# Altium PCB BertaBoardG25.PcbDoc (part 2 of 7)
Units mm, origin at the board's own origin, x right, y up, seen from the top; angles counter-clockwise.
Board outline 160 x 160 mm, 4 copper layers (Top, GND Plane, Power Plane, Bottom), stack 1.344 mm thick; 17 components, 112 nets, 2311 pads, 138 vias.
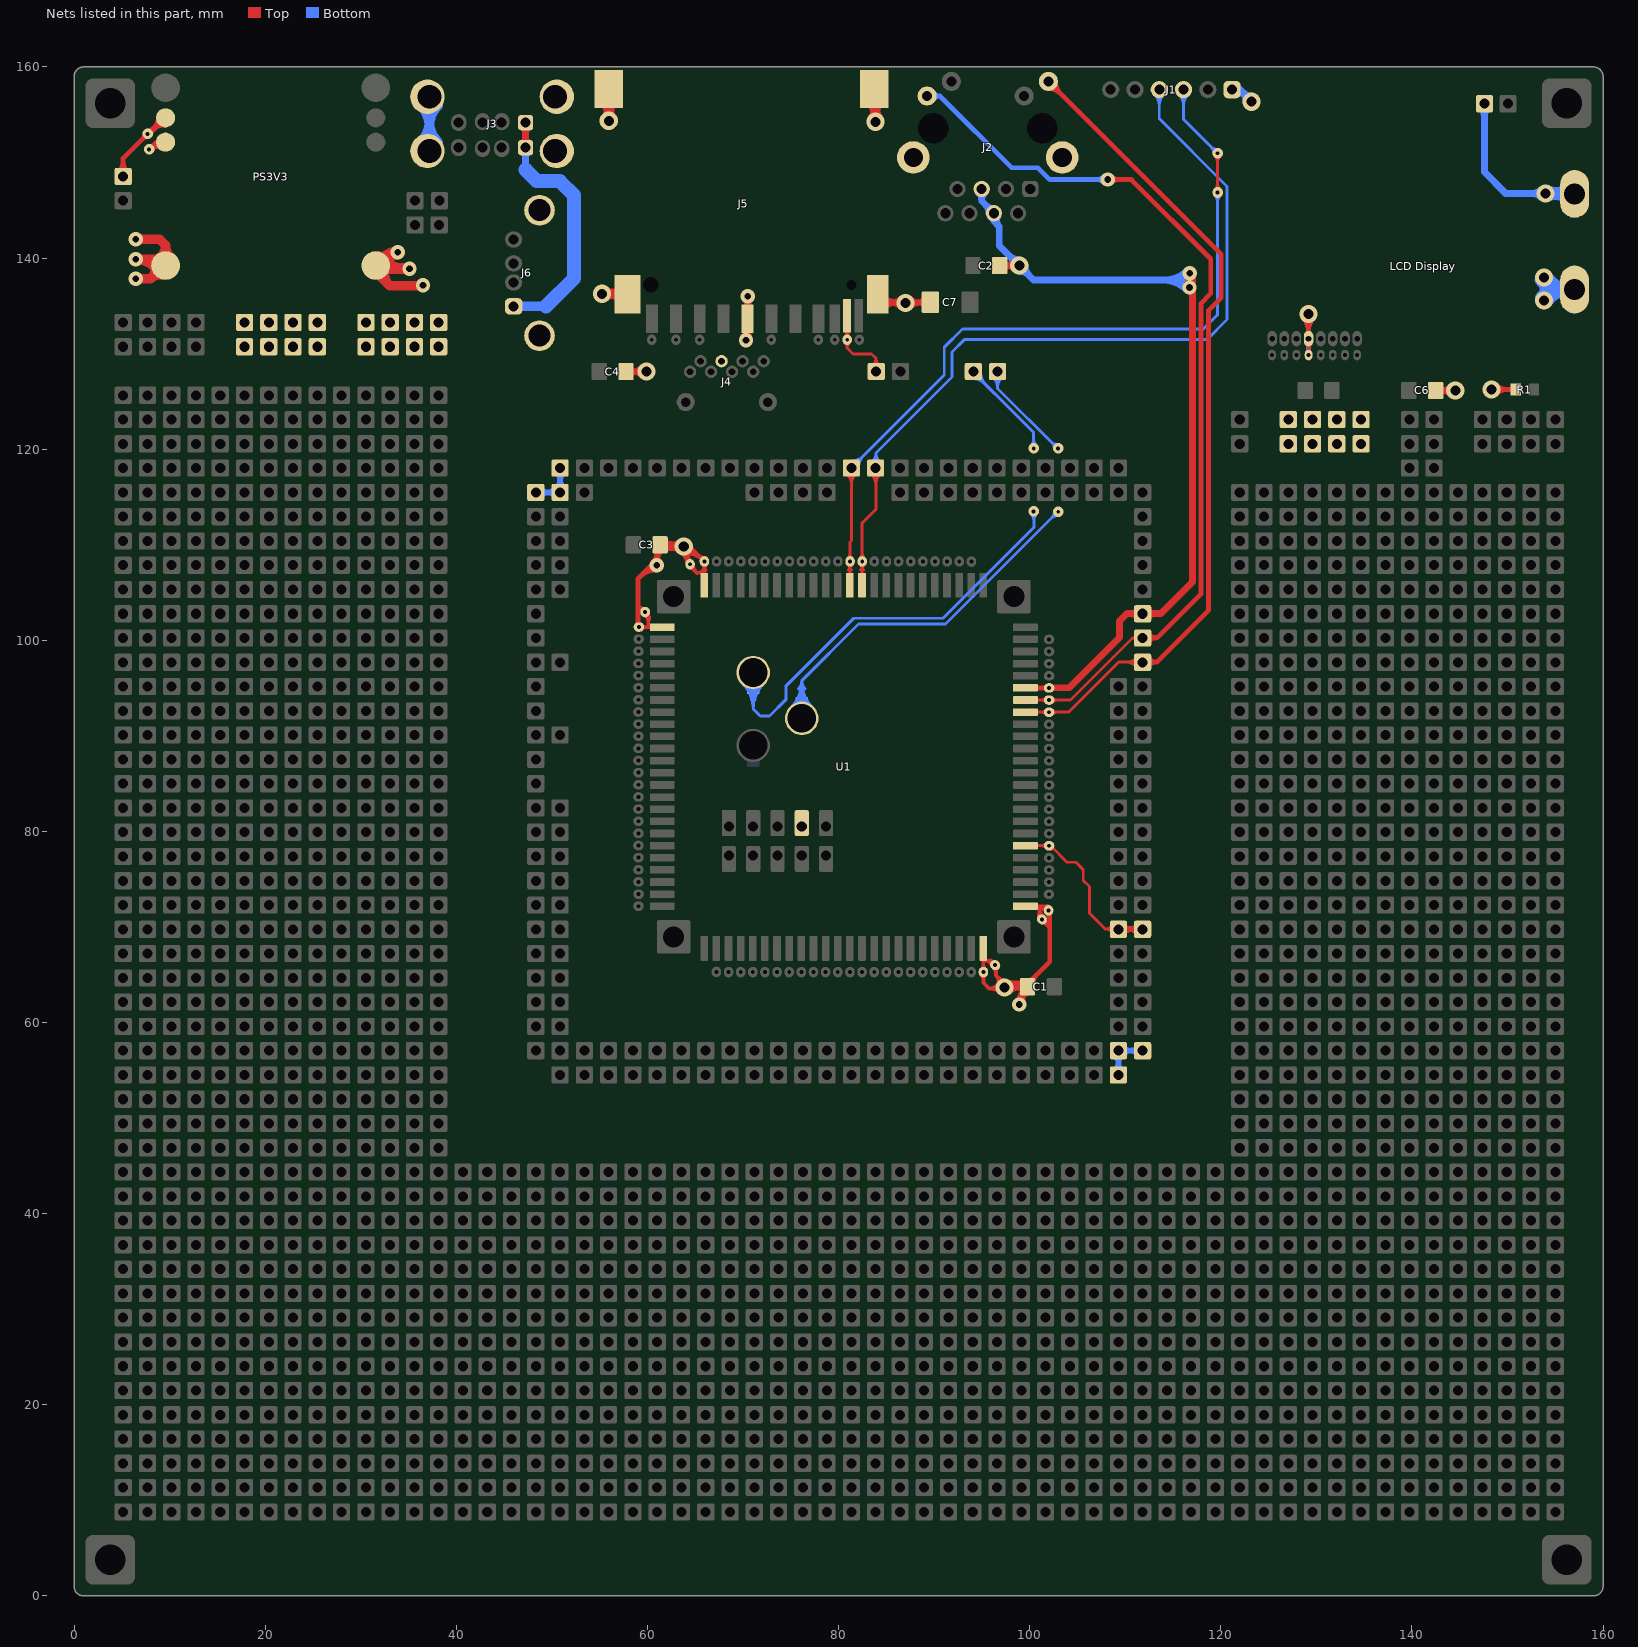
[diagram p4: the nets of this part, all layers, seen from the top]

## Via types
v1: diameter 1.5, hole 0.7, Top to Bottom, tented both sides, 54 vias
v2: diameter 1.1, hole 0.4, Top to Bottom, tented both sides, 49 vias
v3: diameter 1.9, hole 1.05, Top to Bottom, tented both sides, 17 vias
v4: diameter 1.9, hole 1.05, Top to Bottom, 16 vias
v5: diameter 0.9, hole 0.4, Top to Bottom, tented both sides, 2 vias

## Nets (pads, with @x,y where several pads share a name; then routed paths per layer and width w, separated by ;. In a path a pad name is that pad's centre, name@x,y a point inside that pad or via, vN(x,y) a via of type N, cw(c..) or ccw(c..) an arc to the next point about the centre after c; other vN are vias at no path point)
3V3: "LCD Display.4" "LCD Display.9" C1.1 C3.1 C4.1 C6.2 J1.1 J4.4 J5.4 pad.0@17.842,130.72 pad.0@17.842,133.26 pad.0@20.382,130.72 pad.0@20.382,133.26 pad.0@22.922,130.72 pad.0@22.922,133.26 pad.0@25.462,130.72 pad.0@25.462,133.26 pad.0@48.322,115.48 pad.0@50.862,115.48 pad.0@50.862,118.02 pad.0@59.11,101.385 pad.0@59.761,102.96 pad.0@64.464,107.961 pad.0@65.964,108.261 pad.0@95.159,65.279 pad.0@96.387,66.017 pad.0@101.287,70.796 pad.0@101.977,71.74 pad.0@109.282,54.52 pad.0@109.282,57.06 pad.0@111.822,57.06 pad.0@127.062,120.56 pad.0@127.062,123.1 pad.0@129.183,129.853 pad.0@129.602,120.56 pad.0@129.602,123.1 pad.0@132.142,120.56 pad.0@132.142,123.1 pad.0@134.682,120.56 pad.0@134.682,123.1 PS3V3.4 R1.2 U1.7 U1.E24 U1.N1 U1.S1 U1.W24 | length 300.1
  Top w0.3: 128.935,131.014 cw(c128.338,130.416) 129.183,130.416 cw(c130.028,130.416) 129.43,131.014 ; pad.0@129.006,130.179 ccw(c128.579,130.606) 129.183,130.606 ccw(c129.786,130.606) pad.0@129.36,130.179 ; pad.0@129.183,130.168 129.183,131.561 129.183,131.57
  Top w0.35: pad.0@59.267,101.375 U1.E24@61.551,101.375 ; pad.0@59.389,101.155 cw(c59.92,100.624) 59.92,101.375 ; pad.0@59.389,101.614 ccw(c59.968,102.193) 59.968,101.375 ; 60.102,101.375 60.102,102.24 ; U1.E24@60.603,101.375 ccw(c60.603,101.908) U1.E24@61.042,101.604 ; U1.E24@61.272,101.375 ccw(c61.272,101.445) U1.E24@61.329,101.405 ; pad.0@65.734,107.981 cw(c65.221,107.468) 65.946,107.468 ; 65.771,107.311 cw(c65.202,107.772) 65.202,107.04 U1.S1@65.889,107.04 ; 65.787,107.329 ccw(c65.403,107.713) 65.946,107.713 ccw(c66.489,107.713) 66.105,107.329 ; U1.S1@65.946,105.77 pad.0@65.946,108.295 ; 65.946,107.384 cw(c66.79,107.384) pad.0@66.193,107.981 ; pad.0@94.929,65.558 ccw(c94.374,66.113) 95.159,66.113 ccw(c95.943,66.113) pad.0@95.389,65.558 ; U1.N1@94.997,67.211 cw(c94.607,66.82) U1.N1@95.159,66.82 ; U1.N1@95.156,67.77 95.159,67.767 pad.0@95.159,65.279 ; U1.N1@95.159,66.833 cw(c95.693,66.833) U1.N1@95.315,67.211 ; 95.729,66.5 cw(c95.729,65.805) pad.0@96.375,66.061 ; 95.901,66.5 95.213,66.5 cw(c95.213,65.6) pad.0@96.05,65.932 ; U1.W24@99.551,72.165 pad.0@101.836,72.165 ; U1.W24@99.773,72.195 ccw(c99.831,72.235) U1.W24@99.831,72.165 ; U1.W24@100.064,72.348 ccw(c100.502,72.652) U1.W24@100.502,72.118 ; U1.W24@100.289,72.165 cw(c100.289,70.102) pad.0@101.747,71.561 ; U1.W24@100.496,72.348 cw(c99.613,71.062) pad.0@101.172,71.062 ; 101.001,71.3 101.001,72.165 ccw(c102.505,72.165) pad.0@101.475,71.069 ; 101.001,71.355 ccw(c101.744,71.355) pad.0@101.235,70.813 ; 101.134,72.165 cw(c101.134,70.947) pad.0@101.995,71.808
  Top w0.4: C3.1@61.49,110.008 ccw(c62.373,110.654) 62.373,109.56 ; C3.1@61.753,109.666 cw(c62.945,108.474) v4@62.945,110.16 ; C3.1@61.753,110.514 ccw(c62.609,111.371) 62.609,110.16 ; C3.1@61.813,110.244 ccw(c63.161,111.23) v4@63.161,109.56 ; C3.1@61.902,109.34 C3.1@62.122,109.56 ; 62.447,110.16 cw(c62.447,108.834) v4@63.519,109.614 ; 62.618,109.56 cw(c62.618,108.636) v4@63.271,109.289 ; 62.787,109.56 ccw(c62.787,110.358) v4@63.493,109.984 ; 62.812,110.16 ccw(c62.812,110.809) v4@63.271,110.35 ; v4@63.139,110.171 cw(c62.122,110.712) C3.1@62.122,109.56 ; v4@63.195,109.378 ccw(c61.661,108.263) 61.661,110.16 64.082,110.16 65.946,108.295 ccw(c64.054,106.404) v4@63.857,109.072 ; v4@63.76,109.846 ccw(c64.432,109.417) 63.868,108.853 ; v4@63.798,109.869 cw(c63.884,108.703) 64.711,109.53 ; v4@63.828,109.47 cw(c63.969,107.553) 65.329,108.913 ; v4@64.097,109.631 ccw(c64.861,109.143) 64.22,108.501 ; pad.0@64.164,108.015 ccw(c62.892,108.03) v4@63.791,108.93 ; v4@64.434,109.416 ccw(c65.291,108.868) pad.0@64.572,108.149 ; pad.0@64.464,107.611 cw(c64.464,107.208) 64.748,107.493 ; pad.0@64.764,107.911 ccw(c65.809,107.911) 65.07,107.171 ; 65.202,107.04 64.572,107.67 pad.0@64.572,108.149 ; 65.395,108.847 ccw(c65.964,109.415) pad.0@65.964,108.611 ; 65.475,108.766 cw(c65.019,108.311) pad.0@65.664,108.311 ; pad.0@94.947,65.016 cw(c94.441,64.51) 95.156,64.51 ; 95.156,64.498 cw(c95.889,64.498) pad.0@95.371,65.016 ; pad.0@95.156,65.279 95.156,64.165 95.761,63.56 ; 95.86,63.56 cw(c95.86,62.159) v4@96.851,63.149 ; pad.0@96.053,66.079 ccw(c95.527,66.126) 95.901,66.5 ; pad.0@96.211,65.769 cw(c95.571,65.129) 96.476,65.129 ; pad.0@96.321,66.351 cw(c96.268,66.867) 95.901,66.5 ; 96.476,65.385 cw(c97.019,65.385) pad.0@96.635,65.769 ; v4@96.683,63.953 ccw(c95.821,64.291) 96.476,64.945 ; 96.715,64.705 ccw(c97.381,65.371) v4@97.381,64.43 ; v4@96.756,64.094 cw(c95.761,64.753) 95.761,63.56 ; 96.908,64.513 cw(c96.442,64.048) v4@97.055,63.807 ; v4@97.479,64.2 cw(c97.479,61.555) C1.1@99.35,63.425 ; v4@97.71,63.559 cw(c98.628,63.222) 98.628,64.2 ; v4@97.911,63.149 cw(c98.902,62.159) 98.902,63.56 ; v4@98.015,64.08 ccw(c98.96,64.678) 98.96,63.56 ; v4@98.036,63.315 cw(c98.663,62.966) 98.477,63.658 ; v4@98.085,63.421 cw(c99.201,63.012) 99.201,64.2 97.221,64.2 96.476,64.945 ; v4@98.109,63.56 ccw(c98.109,65.314) C1.1@99.349,64.074 ; 98.445,64.2 cw(c98.445,62.52) C1.1@99.632,63.708 ; 98.542,63.56 cw(c98.542,62.417) C1.1@99.349,63.225 ; C1.1@99.182,63.747 cw(c98.96,63.784) 98.96,63.56 ; C1.1@99.233,63.388 ccw(c98.96,63.256) 98.96,63.56 ; C3.1@62.122,109.56 v4@63.161,109.56 ; v4@63.161,109.56 v4@63.791,108.93 ; v4@63.791,108.93 pad.0@64.572,108.149 ; 95.761,63.56 98.96,63.56 ; 95.901,66.5 96.476,65.925 96.476,64.945
  Top w0.5: C4.1@57.759,128.122 v4@59.9,128.122 ; C4.1@58.148,127.733 cw(c59.087,126.794) 59.087,128.122 cw(c59.087,129.45) C4.1@58.148,128.511 ; C4.1@58.208,128.122 cw(c58.208,126.427) v4@59.406,127.625 ; C4.1@58.215,128.122 ccw(c58.215,129.807) v4@59.406,128.615 ; 59.002,102.128 ccw(c59.803,102.128) pad.0@59.236,101.561 ; 59.187,106.625 cw(c60.961,104.851) v1@60.961,107.36 ; pad.0@59.267,101.375 59.002,101.64 59.002,106.44 61.002,108.44 C3.1@61.002,109.44 ; v4@59.272,127.814 ccw(c58.888,127.627) 58.778,128.039 ccw(c58.572,128.809) v4@59.28,128.442 ; v4@59.274,128.432 cw(c58.886,128.625) 58.773,128.206 cw(c58.565,127.429) v4@59.28,127.798 ; pad.0@59.702,102.667 cw(c59.578,102.158) 60.102,102.158 ; pad.0@59.745,103.259 cw(c59.683,104.221) 59.002,103.54 60.102,102.44 ; pad.0@60.001,102.838 ccw(c60.386,102.724) 60.102,102.44 ; 60.04,107.478 cw(c60.961,106.558) v1(60.961,107.86) ; 60.102,102.24 60.102,102.44 ; v1@60.608,108.213 ccw(c59.656,109.165) C3.1@61.002,109.165 ; v1@60.714,108.294 ccw(c60.296,109.026) 61.11,108.808 ccw(c61.649,108.664) v1@61.286,108.24 ; v1@61.002,108.403 cw(c62.151,108.403) C3.1@61.595,109.409 ; 61.002,108.969 ccw(c62.07,108.969) v1@61.315,108.213 ; v1@98.651,62.333 ccw(c98.26,63.01) 99.015,62.808 ; v1@98.694,62.355 ccw(c98.548,62.676) 98.901,62.676 ; v1@98.901,61.694 cw(c100.405,61.694) C1.1@99.943,63.126 ; v1@98.901,62.381 cw(c100.183,62.381) C1.1@99.789,63.602 ; 99.006,62.781 cw(c99.774,62.013) C1.1@99.774,63.099 ; 99.017,62.814 ccw(c99.48,62.69) v1@99.196,62.303 ; v1@99.107,62.355 cw(c99.253,62.676) 98.901,62.676 ; C1.1@99.172,62.948 ccw(c99.928,62.193) v1(98.901,61.9) 98.901,62.676 ; C1.1@99.227,63.593 cw(c98.099,63.478) 98.901,62.676 ; v1@99.381,62.037 cw(c100.863,62.46) 99.774,63.549 98.901,62.676 ; C1.1@99.774,64.399 ccw(c99.774,65.226) C1.1@100.358,64.641 ; C1.1@100.101,64.1 100.101,64.384 102.101,66.384 102.101,71.9 pad.0@101.836,72.165 ; C1.1@100.324,63.849 cw(c102.153,63.849) 100.859,65.143 ; 101.001,71.3 101.001,71.1 102.101,70 ; pad.0@101.323,70.511 cw(c101.323,69.867) 101.778,70.322 ; pad.0@101.573,70.761 ccw(c102.136,70.761) 101.738,70.363 ; pad.0@101.8,71.514 cw(c101.076,70.789) 102.101,70.789 ; v3@128.666,133.665 cw(c127.419,132.418) 129.183,132.418 ; 129.006,132.038 ccw(c128.579,132.465) 129.183,132.465 ccw(c129.786,132.465) 129.36,132.038 ; v3(129.161,134.16) 129.183,134.138 129.183,131.561 ; 129.183,132.522 cw(c130.799,132.522) v3@129.656,133.665 ; C6.2@142.479,126.143 v4(144.537,126.144) ; C6.2@142.844,126.143 ccw(c142.844,127.838) v4@144.042,126.639 ; C6.2@142.851,126.143 cw(c142.851,124.458) v4@144.042,125.649 ; C6.2@142.868,125.754 cw(c143.807,124.815) 143.807,126.143 cw(c143.807,127.471) C6.2@142.868,126.532 ; v4@143.897,125.863 ccw(c143.29,125.596) 143.462,126.236 ccw(c143.56,126.602) v4@143.903,126.441 ; v4@143.896,126.426 cw(c143.284,126.695) 143.457,126.049 cw(c143.557,125.676) v4@143.906,125.843 ; v4@148.31,126.24 R1.2@150.451,126.24 ; v4@148.804,125.749 cw(c149.988,124.566) 149.988,126.24 ; v4@148.804,126.739 ccw(c150.01,127.946) 150.01,126.24 ; 150.137,126.24 ccw(c150.137,126.975) R1.2@150.657,126.455 ; 150.153,126.24 cw(c150.153,125.527) R1.2@150.657,126.031
  Top w0.7: v1@70.028,131.693 ccw(c68.943,132.778) J5.4@70.477,132.778 ; v1@70.111,131.756 ccw(c69.664,132.53) J5.4@70.527,132.298 ; v1@70.218,135.717 cw(c69.591,135.091) J5.4@70.477,135.091 ; J5.4@70.283,132.583 cw(c69.813,132.114) 70.477,132.114 cw(c71.141,132.114) J5.4@70.672,132.583 ; J5.4@70.283,134.722 ccw(c69.813,135.192) 70.477,135.192 ccw(c71.141,135.192) J5.4@70.672,134.722 ; v1@70.477,131.5 J5.4@70.477,133.653 v1@70.477,136 ; J5.4@70.477,134.978 cw(c71.523,134.978) v1@70.783,135.717 ; J5.4@70.553,132.398 ccw(c71.556,132.129) v1@70.657,131.61
  Top w1: v1(6.447,141.967) 8.947,141.967 9.579,141.335 ; v1(6.457,137.837) 8.017,137.837 9.398,139.219 PS3V3.4@9.579,139.219 ; PS3V3.4@8.579,139.21 cw(c6.659,139.195) 8.017,137.837 cw(c9.066,136.788) PS3V3.4@9.373,138.24 ; PS3V3.4@8.755,138.653 ccw(c6.447,137.068) v1(6.447,139.867) 8.93,139.867 PS3V3.4@9.579,139.219 ; PS3V3.4@8.944,139.991 ccw(c7.839,141.335) 9.579,141.335 ; PS3V3.4@10.214,139.991 cw(c11.319,141.335) 9.579,141.335 ; PS3V3.4@9.579,139.219 9.579,141.335
  Bottom w0.35: pad.0@48.322,115.48 pad.0@50.862,115.48 pad.0@50.862,118.02 ; pad.0@48.587,115.214 cw(c49.227,114.574) 49.227,115.48 cw(c49.227,116.385) pad.0@48.587,115.745 ; pad.0@48.834,114.967 cw(c50.072,113.729) 50.072,115.48 cw(c50.072,117.23) pad.0@48.834,115.992 ; pad.0@48.919,115.069 cw(c49.471,114.69) 49.645,115.337 ; pad.0@48.919,115.89 ccw(c49.471,116.269) 49.645,115.622 ; pad.0@48.95,115.117 cw(c49.861,114.591) 49.589,115.607 ; pad.0@48.95,115.842 ccw(c49.861,116.368) 49.589,115.352 ; pad.0@50.349,114.967 ccw(c49.111,113.729) 49.111,115.48 ccw(c49.111,117.23) 50.349,115.992 ccw(c49.111,117.23) 50.862,117.23 ccw(c52.612,117.23) pad.0@51.374,115.992 ; pad.0@50.349,117.507 cw(c49.111,116.269) 50.862,116.269 cw(c52.612,116.269) pad.0@51.374,117.507 ; pad.0@50.451,117.422 cw(c50.072,116.87) 50.719,116.697 ; pad.0@50.499,117.392 cw(c49.973,116.48) 50.99,116.753 ; pad.0@50.597,115.214 ccw(c49.956,114.574) 49.956,115.48 ccw(c49.956,116.385) 50.597,115.745 ccw(c49.956,116.385) 50.862,116.385 ccw(c51.767,116.385) pad.0@51.127,115.745 ; pad.0@50.597,117.754 cw(c49.956,117.114) 50.862,117.114 cw(c51.767,117.114) pad.0@51.127,117.754 ; 50.734,116.753 cw(c51.75,116.48) pad.0@51.224,117.392 ; 51.005,116.697 cw(c51.651,116.87) pad.0@51.272,117.422 ; pad.0@108.769,55.032 ccw(c107.531,56.27) 109.282,56.27 ccw(c111.032,56.27) pad.0@109.794,55.032 ; pad.0@108.769,56.547 cw(c107.531,55.309) 109.282,55.309 cw(c111.032,55.309) 109.794,56.547 cw(c111.032,55.309) 111.032,57.06 cw(c111.032,58.81) pad.0@109.794,57.572 ; pad.0@108.871,56.462 cw(c108.492,55.91) 109.139,55.737 ; pad.0@108.919,56.432 cw(c108.393,55.52) 109.41,55.793 ; pad.0@109.017,54.785 ccw(c108.376,55.425) 109.282,55.425 ccw(c110.187,55.425) pad.0@109.547,54.785 ; pad.0@109.017,56.794 cw(c108.376,56.154) 109.282,56.154 cw(c110.187,56.154) 109.547,56.794 cw(c110.187,56.154) 110.187,57.06 cw(c110.187,57.965) pad.0@109.547,57.325 ; 109.154,55.793 cw(c110.17,55.52) pad.0@109.644,56.432 ; pad.0@109.282,54.52 pad.0@109.282,57.06 pad.0@111.822,57.06 ; 109.425,55.737 cw(c110.071,55.91) pad.0@109.692,56.462 ; pad.0@109.879,56.649 cw(c110.431,56.27) 110.605,56.917 ; pad.0@109.879,57.47 ccw(c110.431,57.849) 110.605,57.202 ; pad.0@109.91,56.697 cw(c110.821,56.171) 110.549,57.187 ; pad.0@109.91,57.422 ccw(c110.821,57.948) 110.549,56.932 ; pad.0@111.309,56.547 ccw(c110.071,55.309) 110.071,57.06 ccw(c110.071,58.81) pad.0@111.309,57.572 ; pad.0@111.557,56.794 ccw(c110.916,56.154) 110.916,57.06 ccw(c110.916,57.965) pad.0@111.557,57.325
  Bottom w0.5: J1.1@121.055,158 cw(c121.363,157.062) J1.1@122.061,157.76 ; J1.1@121.18,157.62 122.201,157.62 ; J1.1@121.211,157.525 cw(c121.647,156.196) 122.636,157.185 ; J1.1@121.367,157.05 cw(c121.931,155.33) v3@123.211,156.61 ; J1.1@121.704,157.328 cw(c122.201,157.052) 122.201,157.62 ; J1.1@121.704,157.912 ccw(c122.201,158.188) 122.201,157.62 ; J1.1@121.795,157.67 cw(c121.079,156.429) v3@122.511,156.382 ; 122.443,157.378 ccw(c123.211,158.146) v3@123.211,157.06 ; 122.518,157.253 cw(c122.025,156.398) v3@123.011,156.366 ; v3@122.527,156.509 ccw(c121.346,156.766) 122.201,157.62 ; v3(123.211,156.36) v3@123.211,156.61 ; v3@128.666,133.665 cw(c127.419,132.418) 129.183,132.418 ; 129.006,131.085 cw(c128.579,130.658) 129.183,130.658 cw(c129.786,130.658) 129.36,131.085 ; 129.006,132.038 ccw(c128.579,132.465) 129.183,132.465 ccw(c129.786,132.465) 129.36,132.038 ; pad.0@129.161,130.16 129.183,130.181 129.183,131.561 129.183,134.138 v3(129.161,134.16) ; 129.183,132.522 cw(c130.799,132.522) v3@129.656,133.665 ; 122.201,157.62 v3@123.211,156.61
  Bottom w1: v3@153.345,137.668 ccw(c155.071,138.747) 155.071,136.711 ; v3@153.36,135.874 cw(c154.962,134.759) 154.962,136.711 ; 153.868,136.711 156.876,136.711 ; v3@154.181,135.303 cw(c156.876,133.429) 156.876,136.711 ; v3@154.193,138.198 ccw(c156.876,139.876) 156.876,136.711 ; 156.311,136.004 ccw(c154.604,134.297) 154.604,136.711 ccw(c154.603,139.126) 156.311,137.418
  other v1: 70.311,131.41 70.501,136
  other v3: 153.811,135.56 153.811,137.96
  other v4: 97.381,63.68 63.802,109.819 148.309,126.244 59.901,128.12
"3V3 ETH": C2.1 J2.4 J2.5 pad.0@102.032,95.017 pad.0@111.822,102.78 U1.W6 | length 117.5
  Top w0.5: C2.1@96.858,139.211 v4(98.916,139.213) ; C2.1@97.223,139.211 ccw(c97.223,140.906) v4@98.421,139.708 ; C2.1@97.23,139.211 cw(c97.23,137.526) v4@98.421,138.718 ; C2.1@97.247,138.822 cw(c98.186,137.883) 98.186,139.211 cw(c98.186,140.539) C2.1@97.247,139.6 ; v4@98.276,138.931 ccw(c97.669,138.664) 97.841,139.304 ccw(c97.939,139.67) v4@98.282,139.509 ; v4@98.276,139.494 cw(c97.663,139.764) 97.836,139.117 cw(c97.936,138.744) v4@98.285,138.911 ; 100.891,95.02 100.894,95.017 pad.0@102.032,95.017 ; pad.0@101.806,94.841 ccw(c101.379,94.414) 101.379,95.017 ccw(c101.379,95.621) pad.0@101.806,95.194
  Top w0.7: pad.0@102.032,95.025 104.126,95.025 109.401,100.299 109.401,102.02 110.19,102.81 pad.0@111.741,102.81 ; 110.421,102.81 cw(c110.421,101.379) pad.0@111.433,102.391 ; 110.567,102.81 ccw(c110.567,104.035) pad.0@111.433,103.168 ; pad.0@111.691,102.76 pad.0@111.741,102.81 ; pad.0@111.831,102.9 pad.0@111.741,102.81 ; pad.0@112.211,102.391 cw(c113.222,101.379) 113.222,102.81 ; pad.0@112.211,103.168 ccw(c113.077,104.035) 113.077,102.81 ; v1@116.469,137.231 ccw(c115.514,138.41) 117.031,138.41 117.031,106.1 113.741,102.81 pad.0@111.741,102.81 ; v1@116.478,138.127 cw(c115.142,136.791) v1@117.031,136.791
  Bottom w0.7: J2.5@94.626,146.874 cw(c93.772,146.021) 94.979,146.021 cw(c96.186,146.021) J2.5@95.333,146.874 ; J2.5@94.979,147.228 94.979,145.958 J2.4@96.249,144.688 96.249,143.851 96.801,143.3 ; J2.4@95.749,144.688 ccw(c94.542,144.688) 95.396,145.541 ccw(c96.249,146.395) J2.4@96.249,145.188 ; J2.4@96.673,144.422 ccw(c97.442,143.941) 96.801,143.3 ; 97.878,140.243 ccw(c98.916,141.281) v4@98.916,139.813 ; 97.898,140.223 cw(c96.888,139.213) v4@98.316,139.213 ; v4@98.916,138.613 cw(c98.916,137.184) 99.927,138.194 ; v4@99.516,139.213 ccw(c100.985,139.213) 99.946,138.174 ; 113.848,137.71 cw(c113.848,134.047) v1@116.438,136.637 ; 114.105,137.71 ccw(c114.105,141.066) v1@116.478,138.693 ; 115.538,137.71 cw(c115.538,135.737) v1@116.933,137.132 ; 115.795,137.71 ccw(c115.795,139.376) v1@116.973,138.198 ; v1@116.941,137.71 100.411,137.71 96.801,141.32 96.801,143.3
  other v1: 116.721,136.92 116.761,138.41
3V3AUX: PS3V3.3 | length 7.4
  Top w0.5: v2@7.861,151.66 ccw(c7.861,152.384) 8.373,151.872 ccw(c8.885,151.36) v2@8.161,151.36 ; v2@8.151,151.282 cw(c9.379,150.953) PS3V3.3@8.743,152.054 ; v2@8.159,151.398 cw(c8.602,151.456) 8.379,151.843 ; 8.299,151.797 cw(c8.946,151.15) PS3V3.3@9.443,151.919 ; PS3V3.3@9.172,151.499 ccw(c8.602,150.618) v2(7.861,151.36) 8.63,152.129 PS3V3.3@9.579,152.129
5V0: J3.1 J3.5 J6.1 pad.0@30.542,130.72 pad.0@30.542,133.26 pad.0@33.082,130.72 pad.0@33.082,133.26 pad.0@35.622,130.72 pad.0@35.622,133.26 pad.0@38.162,130.72 pad.0@38.162,133.26 PS3V3.5 | length 65.8
  Top w0.7: J3.1@46.934,151.871 ccw(c46.166,152.639) 47.252,152.639 ccw(c48.339,152.639) J3.1@47.57,151.871 ; J3.5@46.934,153.855 cw(c46.166,153.086) 47.252,153.086 cw(c48.339,153.086) J3.5@47.57,153.855 ; J3.1@47.252,151.553 J3.5@47.252,154.173
  Top w1: PS3V3.5@31.785,140.197 ccw(c32.092,141.649) v1@33.141,140.6 ; PS3V3.5@32.205,139.664 cw(c33.861,138.008) v1@33.861,140.35 ; PS3V3.5@32.228,138.57 PS3V3.5@31.579,139.219 ; PS3V3.5@32.286,138.511 cw(c33.072,137.725) 33.072,138.837 ; PS3V3.5@32.286,139.926 ccw(c34.914,142.554) v1@34.914,138.837 ; PS3V3.5@32.464,139.428 cw(c34.082,138.494) v1@33.887,140.351 ; PS3V3.5@32.541,138.945 ccw(c34.347,138.43) 33.019,137.102 ; PS3V3.5@32.579,139.227 cw(c34.499,139.242) v1@33.141,140.6 ; PS3V3.5@32.584,138.837 v1@35.067,138.837 ; 32.656,140.32 cw(c33.258,139.277) v1@33.757,140.372 ; v1(33.861,140.6) v1@33.141,140.6 ; 34.314,138.998 ccw(c34.544,139.853) v1@34.986,139.086 ; 35.744,137.102 ccw(c35.744,137.937) v1@36.334,137.347 ; v1(36.511,137.17) 36.443,137.102 33.019,137.102 ; PS3V3.5@31.579,139.219 31.76,139.219 v1@33.141,140.6 ; PS3V3.5@31.579,139.219 31.579,138.542 33.019,137.102
  Bottom w0.7: J3.1@46.934,151.235 cw(c46.166,150.466) 47.252,150.466 cw(c48.339,150.466) J3.1@47.57,151.235 ; J3.1@46.934,151.871 ccw(c46.166,152.639) 47.252,152.639 ccw(c48.339,152.639) J3.1@47.57,151.871 ; J3.5@46.934,153.855 cw(c46.166,153.086) 47.252,153.086 cw(c48.339,153.086) J3.5@47.57,153.855 ; 47.252,149.229 J3.1@47.252,151.553 J3.5@47.252,154.173
  Bottom w1: J6.1@46.009,134.947 49.388,134.947
  Bottom w1.5: 47.252,149.229 48.411,148.07 50.811,148.07 52.311,146.57 52.311,137.87 49.388,134.947
  other v1: 35.111,138.87
ADVREF: pad.0@102.032,78.507 pad.0@109.282,69.76 pad.0@111.822,69.76 U1.W19 | length 52.5
  Top w0.3: U1.W19@99.551,78.515 102.186,78.515 103.921,76.78 104.831,76.78 105.611,76 105.611,74.878 106.261,74.228 106.261,71.439 107.911,69.79 ; U1.W19@99.978,78.57 ccw(c100.104,78.689) U1.W19@100.104,78.515 ; U1.W19@100.191,78.723 ccw(c100.793,79.289) U1.W19@100.793,78.463 ; pad.0@102.059,78.18 102.468,78.18 ; pad.0@108.637,69.376 ccw(c107.911,68.945) 107.911,69.79 ; pad.0@108.664,70.185 cw(c107.911,70.705) 107.911,69.79 ; pad.0@109.6,69.441 cw(c110.441,68.6) 110.441,69.79 ; pad.0@109.6,70.078 ccw(c110.295,70.773) 110.295,69.79 ; pad.0@109.812,69.229 cw(c111.165,67.876) pad.0@111.165,69.79 ; pad.0@109.812,70.29 ccw(c111.02,71.497) pad.0@111.02,69.79 ; pad.0@109.938,69.79 cw(c109.938,67.876) pad.0@111.291,69.229 ; pad.0@110.084,69.79 ccw(c110.084,71.497) pad.0@111.291,70.29 ; 110.663,69.79 cw(c110.663,68.6) pad.0@111.504,69.441 ; 110.808,69.79 ccw(c110.808,70.773) pad.0@111.504,70.078 ; 110.888,69.825 ccw(c111.027,70.343) pad.0@111.459,70.026 ; pad.0@111.161,70.114 cw(c110.284,70.583) 110.541,69.623 cw(c110.691,69.065) pad.0@111.183,69.367 ; pad.0@111.168,69.392 ccw(c110.167,68.83) 110.464,69.938 ccw(c110.647,70.621) pad.0@111.217,70.203 ; pad.0@111.831,69.79 107.911,69.79 ; 101.119,78.515 cw(c101.119,77.644) 101.735,78.26 ccw(c101.119,77.644) 101.119,78.515 ; 101.155,78.515 ccw(c101.155,79.334) 101.735,78.755 cw(c101.155,79.334) 101.155,78.515
  Bottom w0.3: pad.0@109.291,69.79 pad.0@111.831,69.79 ; pad.0@109.6,69.441 cw(c110.441,68.6) 110.441,69.79 ; pad.0@109.6,70.078 ccw(c110.295,70.773) 110.295,69.79 ; pad.0@109.812,69.229 cw(c111.165,67.876) pad.0@111.165,69.79 ; pad.0@109.812,70.29 ccw(c111.02,71.497) pad.0@111.02,69.79 ; pad.0@109.938,69.79 cw(c109.938,67.876) pad.0@111.291,69.229 ; pad.0@110.084,69.79 ccw(c110.084,71.497) pad.0@111.291,70.29 ; 110.663,69.79 cw(c110.663,68.6) pad.0@111.504,69.441 ; 110.808,69.79 ccw(c110.808,70.773) pad.0@111.504,70.078 ; 110.888,69.825 ccw(c111.027,70.343) pad.0@111.459,70.026 ; pad.0@111.161,70.114 cw(c110.284,70.583) 110.541,69.623 cw(c110.691,69.065) pad.0@111.183,69.367 ; pad.0@111.168,69.392 ccw(c110.167,68.83) 110.464,69.938 ccw(c110.647,70.621) pad.0@111.217,70.203
CATHODE: "LCD Display.10" pad.0@147.581,156.15 | length 29.8
  Bottom w0.5: 156.969,146.76 157.018,146.711
  Bottom w0.75: pad.0@147.21,155.778 cw(c146.314,154.882) 147.581,154.882 cw(c148.849,154.882) pad.0@147.952,155.778 ; pad.0@147.581,156.15 147.581,148.99 149.811,146.76 v3(153.961,146.76) ; v3@153.555,146.353 ccw(c152.573,145.372) 152.573,146.76 ccw(c152.573,148.148) v3@153.555,147.166
  Bottom w1: v3(153.961,146.76) 156.969,146.76 ; v3@154.186,146.37 cw(c154.962,145.027) 155.363,146.525 ; v3@154.187,147.149 ccw(c155.063,148.662) 155.516,146.973 ; v3@154.279,146.442 cw(c155.048,145.673) 155.048,146.76 cw(c155.048,147.846) v3@154.279,147.078 ; v3@154.487,146.76 cw(c154.487,144.18) 156.311,146.004 ; v3@154.72,146.76 ccw(c154.72,149.009) 156.311,147.418
CD: J5.CD pad.0@80.904,131.451 pad.0@83.942,128.12 | length 15.2
  Top w0.3: pad.0@80.656,131.748 ccw(c80.062,132.343) J5.CD@80.902,132.343 ; pad.0@80.66,131.149 cw(c80.108,130.579) 80.902,130.579 ; J5.CD@80.708,132.433 cw(c80.238,131.964) 80.902,131.964 cw(c81.566,131.964) J5.CD@81.097,132.433 ; J5.CD@80.714,132.427 cw(c80.45,132.146) 80.823,132.046 ; J5.CD@80.765,132.39 cw(c80.556,132.028) 80.959,132.136 ; 80.848,132.139 cw(c81.246,132.033) J5.CD@81.04,132.39 ; J5.CD@80.902,132.349 ccw(c81.752,132.349) pad.0@81.151,131.748 ; J5.CD@80.902,133.953 80.902,130.579 ; 80.984,132.045 cw(c81.36,132.146) J5.CD@81.092,132.428 ; pad.0@81.145,131.148 ccw(c81.69,130.579) 80.902,130.579 ; pad.0@83.509,128.732 ccw(c82.959,129.509) 83.911,129.509 ; pad.0@83.911,128.089 83.911,129.51 ; pad.0@84.332,128.76 cw(c84.789,129.509) 83.911,129.509 ; 80.902,130.579 81.521,129.96 83.461,129.96 83.911,129.51
DIBN: pad.0@94.102,128.12 U1.13 | length 80.5
  Bottom w0.3: U1.13@69.951,95.487 cw(c67.337,92.821) 71.071,92.821 ; U1.13@70.161,95.701 cw(c68.037,93.535) 71.071,93.535 cw(c74.105,93.535) U1.13@71.981,95.701 ; U1.13@70.371,95.916 cw(c68.737,94.249) 71.071,94.249 cw(c73.405,94.249) U1.13@71.771,95.916 ; U1.13@70.717,94.501 cw(c69.864,93.648) 71.071,93.648 cw(c72.278,93.648) U1.13@71.425,94.501 ; 70.835,94.127 cw(c71.312,94.214) U1.13@71.141,94.668 ; U1.13@70.895,94.387 cw(c70.701,93.871) 71.243,93.773 ; 70.899,93.773 cw(c71.441,93.871) U1.13@71.247,94.387 ; U1.13@71.001,94.668 cw(c70.83,94.214) 71.307,94.127 ; U1.13@71.071,95.505 71.071,92.821 ; U1.13@72.191,95.487 ccw(c74.805,92.821) 71.071,92.821 ; pad.0@94.102,127.37 cw(c94.102,125.716) 95.271,126.885 ; pad.0@94.102,127.67 cw(c94.102,126.741) pad.0@94.758,127.398 ; pad.0@94.102,128.12 94.102,128.054 96.347,125.809 96.362,125.809 100.4,121.771 v2@100.4,120.117 ; pad.0@94.552,128.12 ccw(c95.796,128.12) 94.916,127.24 ; pad.0@94.852,128.12 ccw(c96.82,128.12) 95.428,126.728 ; v2@100.134,113.205 cw(c99.328,112.399) 100.467,112.399 ; v2@100.142,120.37 ccw(c99.519,120.993) 100.4,120.993 ; 100.4,121.112 ccw(c101.45,121.112) v2@100.708,120.37 ; 100.467,112.294 v2@100.467,113.462 ; 100.467,112.645 cw(c101.26,112.645) v2@100.699,113.205 ; 100.47,112.327 100.47,111.843 90.941,102.314 81.597,102.314 74.483,95.2 74.483,93.777 72.781,92.076 71.816,92.076 71.071,92.821
  other v2: 100.417,113.488 100.425,120.087
DIBP: pad.0@96.642,128.12 U1.12 | length 71.8
  Bottom w0.3: U1.12@75.02,92.971 ccw(c72.288,95.702) 76.151,95.702 ccw(c80.014,95.702) U1.12@77.282,92.971 ; U1.12@75.232,92.759 ccw(c73.013,94.978) 76.151,94.978 ccw(c79.29,94.978) U1.12@77.07,92.759 ; U1.12@75.444,92.547 ccw(c73.737,94.254) 76.151,94.254 ccw(c78.565,94.254) U1.12@76.858,92.547 ; 75.797,94.918 ccw(c74.944,95.772) 76.151,95.772 ccw(c77.358,95.772) 76.505,94.918 ; U1.12@76.151,92.965 76.151,95.775 82.1,101.724 91.208,101.724 102.769,113.285 v2@102.769,113.607 ; pad.0@96.123,127.577 cw(c94.964,126.365) 96.642,126.365 ; pad.0@96.331,127.794 cw(c95.635,127.067) 96.642,127.067 cw(c97.648,127.067) pad.0@96.953,127.794 ; pad.0@96.642,128.12 96.642,126.365 ; pad.0@97.16,127.577 ccw(c98.319,126.365) 96.642,126.365 ; 102.205,120.801 ccw(c102.965,121.561) v2@102.965,120.487 ; 102.238,112.754 cw(c102.982,112.011) v2@102.982,113.062 ; 102.314,120.693 cw(c101.708,120.087) v2@102.565,120.087 ; 102.324,112.84 ccw(c101.702,113.462) v2@102.582,113.462 ; v2@102.906,113.462 v2@102.982,113.386 ; v2@102.915,120.092 96.642,126.365
  other v2: 102.982,113.462 102.965,120.087
DRXD: J1.4 pad.0@82.476,108.261 pad.0@83.882,118.02 U1.S14 | length 101.1
  Top w0.3: pad.0@82.229,107.963 cw(c81.679,107.414) 82.456,107.414 ; pad.0@82.229,108.558 ccw(c81.679,109.108) 82.456,109.108 ; 82.279,107.347 ccw(c81.853,107.773) 82.456,107.773 ccw(c83.06,107.773) 82.633,107.347 ; U1.S14@82.456,105.77 82.456,112.255 83.911,113.71 pad.0@83.911,118.03 ; 82.456,107.318 cw(c83.369,107.318) pad.0@82.724,107.963 ; 82.456,109.204 ccw(c83.369,109.204) pad.0@82.724,108.558 ; pad.0@83.351,117.489 cw(c82,116.138) 83.911,116.138 ; pad.0@83.564,117.701 cw(c82.724,116.862) 83.911,116.862 ; 83.911,116.28 cw(c85.621,116.28) pad.0@84.412,117.489 ; 83.911,117.004 cw(c84.897,117.004) pad.0@84.2,117.701
  Bottom w0.3: pad.0@83.422,118.612 ccw(c82.649,119.61) 83.911,119.61 ; pad.0@83.606,118.375 ccw(c83.124,118.998) 83.911,118.998 ; pad.0@83.911,118.06 83.911,119.61 ; 83.911,118.948 ccw(c84.695,118.948) pad.0@84.178,118.358 ; pad.0@84.376,118.584 cw(c85.276,119.61) 83.911,119.61 ; J1.4@113.065,157.125 cw(c111.87,155.93) 113.56,155.93 cw(c115.25,155.93) J1.4@114.055,157.125 ; J1.4@113.277,157.337 cw(c112.594,156.654) 113.56,156.654 cw(c114.526,156.654) J1.4@113.843,157.337 ; J1.4@113.56,157.22 113.56,154.601 120.661,147.5 120.661,133.56 118.561,131.46 93.161,131.46 91.861,130.16 91.861,127.56 83.911,119.61
DTXD: J1.3 pad.0@81.204,108.261 pad.0@81.342,118.02 U1.S13 | length 110.6
  Top w0.3: pad.0@80.956,107.963 cw(c80.401,107.408) 81.186,107.408 ; pad.0@80.956,108.558 ccw(c80.401,109.114) 81.186,109.114 ; 81.009,107.347 ccw(c80.583,107.773) 81.186,107.773 ccw(c81.79,107.773) 81.363,107.347 ; U1.S13@81.186,105.77 81.186,110.285 81.371,110.47 pad.0@81.371,118.03 ; 81.186,107.324 cw(c82.091,107.324) pad.0@81.451,107.963 ; 81.186,109.198 ccw(c82.091,109.198) pad.0@81.451,108.558 ; v2@119.378,147.143 ccw(c118.695,147.825) 119.661,147.825 ccw(c120.627,147.825) v2@119.944,147.143 ; v2@119.378,150.677 cw(c118.695,149.994) 119.661,149.994 cw(c120.627,149.994) v2@119.944,150.677 ; v2(119.661,146.86) v2(119.661,150.96) ; pad.0@80.811,117.489 cw(c79.46,116.138) 81.371,116.138 ccw(c79.46,116.138) pad.0@80.811,117.489 ; pad.0@81.024,117.701 cw(c80.184,116.862) 81.371,116.862 ccw(c80.184,116.862) pad.0@81.024,117.701 ; 81.371,116.28 cw(c83.081,116.28) 81.872,117.489 ccw(c83.081,116.28) 81.371,116.28 ; 81.371,117.004 cw(c82.357,117.004) 81.66,117.701 ccw(c82.357,117.004) 81.371,117.004
  Bottom w0.3: pad.0@81.342,118.47 ccw(c81.342,119.483) pad.0@82.058,118.766 ; pad.0@81.342,118.77 ccw(c81.342,120.507) 82.571,119.279 ; pad.0@81.371,118.06 pad.0@81.371,118.271 ; pad.0@81.79,118.688 81.98,118.688 91.061,127.769 91.061,130.66 92.961,132.56 118.161,132.56 119.661,134.06 v2(119.661,146.86) ; pad.0@81.792,118.02 cw(c82.951,118.02) pad.0@82.131,118.839 ; pad.0@82.092,118.02 cw(c83.975,118.02) 82.643,119.351 ; J1.3@115.605,157.125 cw(c114.41,155.93) 116.1,155.93 cw(c117.79,155.93) J1.3@116.595,157.125 ; J1.3@115.817,157.337 cw(c115.134,156.654) 116.1,156.654 cw(c117.066,156.654) J1.3@116.383,157.337 ; J1.3@116.1,157.22 116.1,154.521 v2(119.661,150.96) ; v2@119.261,150.96 ccw(c118.295,150.96) 118.978,151.643 ccw(c119.661,152.325) v2@119.661,151.36 ; v2@119.378,146.577 cw(c118.695,145.894) 119.661,145.894 cw(c120.627,145.894) v2@119.944,146.577
EARTH: C7.2 J2.13 J2.14 J3.9 J3.10 J3.11 J3.12 J5.10 J5.11 J5.12 J5.13 J6.5 J6.6 | length 84.3
  Top w0.5: J5.11@55.112,156.277 cw(c53.372,154.36) v3(55.961,154.36) ; v3@55.384,136.26 ccw(c55.384,138.721) J5.12@57.124,136.981 ; v3@55.426,154.811 ccw(c54.713,155.413) 55.614,155.654 ccw(c56.516,155.896) v3@56.199,155.018 ; J5.11@55.448,156.647 cw(c54.397,155.489) 55.961,155.489 ; v3@55.466,154.855 ccw(c54.271,156.05) 55.961,156.05 ccw(c57.651,156.05) v3@56.456,154.855 ; v3@55.716,155.015 ccw(c55.375,155.924) 56.313,155.673 ccw(c57.251,155.422) v3@56.501,154.805 ; v3@55.729,135.739 cw(c56.29,135.115) 56.507,135.926 cw(c56.725,136.736) v3@55.927,136.476 ; v3@55.733,136.777 ccw(c56.331,137.433) 56.561,136.575 ccw(c56.813,135.636) v3@55.911,135.998 ; v3@55.756,135.765 cw(c56.951,134.57) 56.951,136.26 cw(c56.951,137.95) v3@55.756,136.755 ; J5.11@55.952,157.703 55.961,157.694 v3(55.961,154.36) ; 55.961,155.505 cw(c57.526,155.505) J5.11@56.462,156.653 ; 56.403,136.26 cw(c56.403,134.82) J5.12@57.461,135.796 ; J5.11@56.802,156.286 ccw(c58.588,154.36) v3(55.961,154.36) ; J5.12@57.094,135.457 ccw(c55.261,133.767) v3(55.261,136.26) 57.845,136.26 J5.12@57.902,136.203 ; J5.10@82.941,156.252 cw(c81.241,154.258) v3@83.861,154.258 ; J5.10@83.265,156.632 cw(c82.165,155.341) 83.861,155.341 ; v3@83.322,154.706 ccw(c82.58,155.32) 83.51,155.569 ccw(c84.439,155.818) v3@84.104,154.916 ; v3@83.366,154.755 ccw(c82.171,155.95) 83.861,155.95 ccw(c85.551,155.95) v3@84.356,154.755 ; v3@83.542,154.883 ccw(c82.96,156.02) 84.194,155.689 ccw(c85.267,155.402) v3@84.405,154.701 ; J5.10@83.752,157.703 83.861,157.594 v3(83.861,154.26) ; v3@83.861,154.448 cw(c86.507,154.448) J5.10@84.636,156.319 ; 83.861,155.655 cw(c85.3,155.655) J5.10@84.282,156.672 ; J5.13@84.102,136.203 85.045,135.26 v4@86.615,135.26 ; J5.13@84.385,135.636 ccw(c85.292,136.543) 85.292,135.26 ; J5.13@84.739,134.716 cw(c86.05,133.404) 86.05,135.26 ; J5.13@84.739,135.989 ccw(c86.499,137.75) v4@86.499,135.26 ; J5.13@85.193,135.26 ccw(c85.193,137.136) v4@86.52,135.809 ; 85.456,135.26 cw(c85.456,133.756) v4@86.52,134.819 ; 85.566,135.51 ccw(c85.806,136.409) v4@86.496,135.784 ; 85.768,135.456 cw(c85.495,134.437) v4@86.409,134.964 ; v4(87.015,135.314) C7.2@89.472,135.314 ; v4@87.51,134.819 cw(c88.705,133.624) 88.705,135.314 cw(c88.705,137.004) v4@87.51,135.809 ; v4@87.571,135.739 ccw(c88.197,136.217) 88.401,135.457 ; v4@87.621,134.964 cw(c88.431,134.497) 88.189,135.4 ; v4@87.869,135.314 ccw(c87.869,137.117) C7.2@89.144,135.842 ; 88.2,135.314 cw(c88.2,133.979) C7.2@89.144,134.923
  Top w1: C7.2@89.472,135.314 C7.2@89.604,135.183
  Bottom w1: J3.12@36.263,152.122 ccw(c34.044,154.341) 37.182,154.341 ccw(c40.321,154.341) J3.12@38.101,152.122 ; J3.11@36.263,155.963 cw(c34.044,153.744) 37.182,153.744 cw(c40.321,153.744) J3.11@38.101,155.963 ; J3.12@37.182,151.203 J3.11@37.182,156.883
EN3V3: pad.0@5.142,148.54 PS3V3.2 | length 16.5
  Top w0.5: pad.0@4.682,148.999 ccw(c3.635,150.046) 5.116,150.046 ; 5.116,150.172 ccw(c6.774,150.172) pad.0@5.601,148.999 ; pad.0@5.142,148.54 5.116,148.565 5.116,150.414 9.37,154.669 PS3V3.2@9.579,154.669 ; 7.178,152.476 cw(c7.706,151.948) v2@7.706,152.695 ; 7.2,152.499 ccw(c6.704,152.995) v2@7.406,152.995 ; v2@7.706,153.295 ccw(c7.706,153.997) 8.202,153.5 ; v2@7.942,153.241 cw(c9.579,151.603) PS3V3.2@9.579,153.919 ; v2@7.995,152.917 cw(c9.007,152.646) 8.483,153.553 ; v2@8.006,152.995 cw(c8.752,152.995) 8.224,153.523 ; 8.446,153.745 ccw(c7.523,154.669) PS3V3.2@8.829,154.669
  other v2: 7.706,152.995
"ETH LED1": J2.12 pad.0@102.032,93.747 pad.0@111.822,100.24 U1.W7 | length 106.9
  Top w0.3: U1.W7@99.551,93.755 104.256,93.755 110.751,100.25 ; U1.W7@99.992,93.795 ccw(c100.089,93.893) U1.W7@100.089,93.755 ; U1.W7@100.204,94.007 ccw(c100.813,94.617) U1.W7@100.813,93.755 ; 101.119,93.755 cw(c101.119,92.884) pad.0@101.735,93.5 ; 101.155,93.755 ccw(c101.155,94.574) pad.0@101.735,93.995 ; pad.0@102.33,93.5 cw(c102.945,92.884) 102.945,93.755 ; pad.0@102.33,93.995 ccw(c102.909,94.574) 102.909,93.755 ; pad.0@111.114,99.993 ccw(c110.751,99.866) 110.751,100.25 ; pad.0@111.12,100.505 cw(c110.751,100.644) 110.751,100.25 ; pad.0@111.831,100.25 110.751,100.25
  Top w0.5: v1@108.161,148.21 110.641,148.21 118.951,139.9 118.951,136.3 117.931,135.28 117.931,104.85 113.351,100.27 ; v1@108.522,147.861 cw(c109.363,147.021) 109.363,148.21 ; v1@108.522,148.569 ccw(c109.388,149.435) 109.388,148.21 ; pad.0@112.281,100.699 ccw(c113.318,101.736) 113.318,100.27 ; pad.0@112.304,99.804 cw(c113.351,98.86) 113.351,100.27 ; pad.0@112.32,100.27 113.351,100.27
  Bottom w0.5: J2.12@89.264,156.958 90.613,156.958 ; J2.12@89.901,156.562 cw(c90.613,156.12) 90.613,156.958 ; J2.12@89.901,157.354 ccw(c90.613,157.796) 90.613,156.958 ; 106.949,148.21 ccw(c106.949,149.435) v1@107.815,148.569 ; 106.974,148.21 cw(c106.974,147.021) v1@107.815,147.861 ; v1@108.161,148.21 102.111,148.21 100.861,149.46 98.111,149.46 90.613,156.958
  other v1: 108.168,148.215
"ETH LED2": J2.9 pad.0@102.032,92.477 pad.0@111.822,97.7 U1.W8 | length 100
  Top w0.3: U1.W8@99.551,92.485 104.086,92.485 109.321,97.72 pad.0@111.831,97.72 ; U1.W8@99.992,92.525 ccw(c100.089,92.623) U1.W8@100.089,92.485 ; U1.W8@100.204,92.737 ccw(c100.813,93.347) U1.W8@100.813,92.485 ; 101.119,92.485 cw(c101.119,91.614) pad.0@101.735,92.23 ; 101.155,92.485 ccw(c101.155,93.304) pad.0@101.735,92.725 ; pad.0@102.33,92.23 cw(c102.945,91.614) 102.945,92.485 ; pad.0@102.33,92.725 ccw(c102.909,93.304) 102.909,92.485 ; 109.962,97.72 cw(c109.962,95.84) pad.0@111.291,97.169 ; 110.06,97.72 ccw(c110.06,99.461) pad.0@111.291,98.23 ; 110.686,97.72 cw(c110.686,96.564) pad.0@111.504,97.381 ; 110.784,97.72 ccw(c110.784,98.737) pad.0@111.504,98.018
  Top w0.5: J2.9@101.964,157.728 cw(c101.964,155.917) 103.244,157.197 cw(c104.525,158.478) J2.9@102.714,158.478 ; J2.9@101.964,158.478 120.051,140.391 120.051,135.85 118.721,134.52 118.721,103.17 113.28,97.73 ; pad.0@111.831,97.73 113.28,97.73 ; pad.0@112.29,98.151 ccw(c113.28,99.106) 113.28,97.73 ; pad.0@112.32,97.282 cw(c113.28,96.475) 113.28,97.73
